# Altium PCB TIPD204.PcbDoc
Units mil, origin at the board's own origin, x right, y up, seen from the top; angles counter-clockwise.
Board outline 2010.03 x 2010.03 mil, 2 copper layers (Top Layer, Bottom Layer), stack 12.8 mil thick; 69 components, 23 nets, 172 pads, 35 vias.
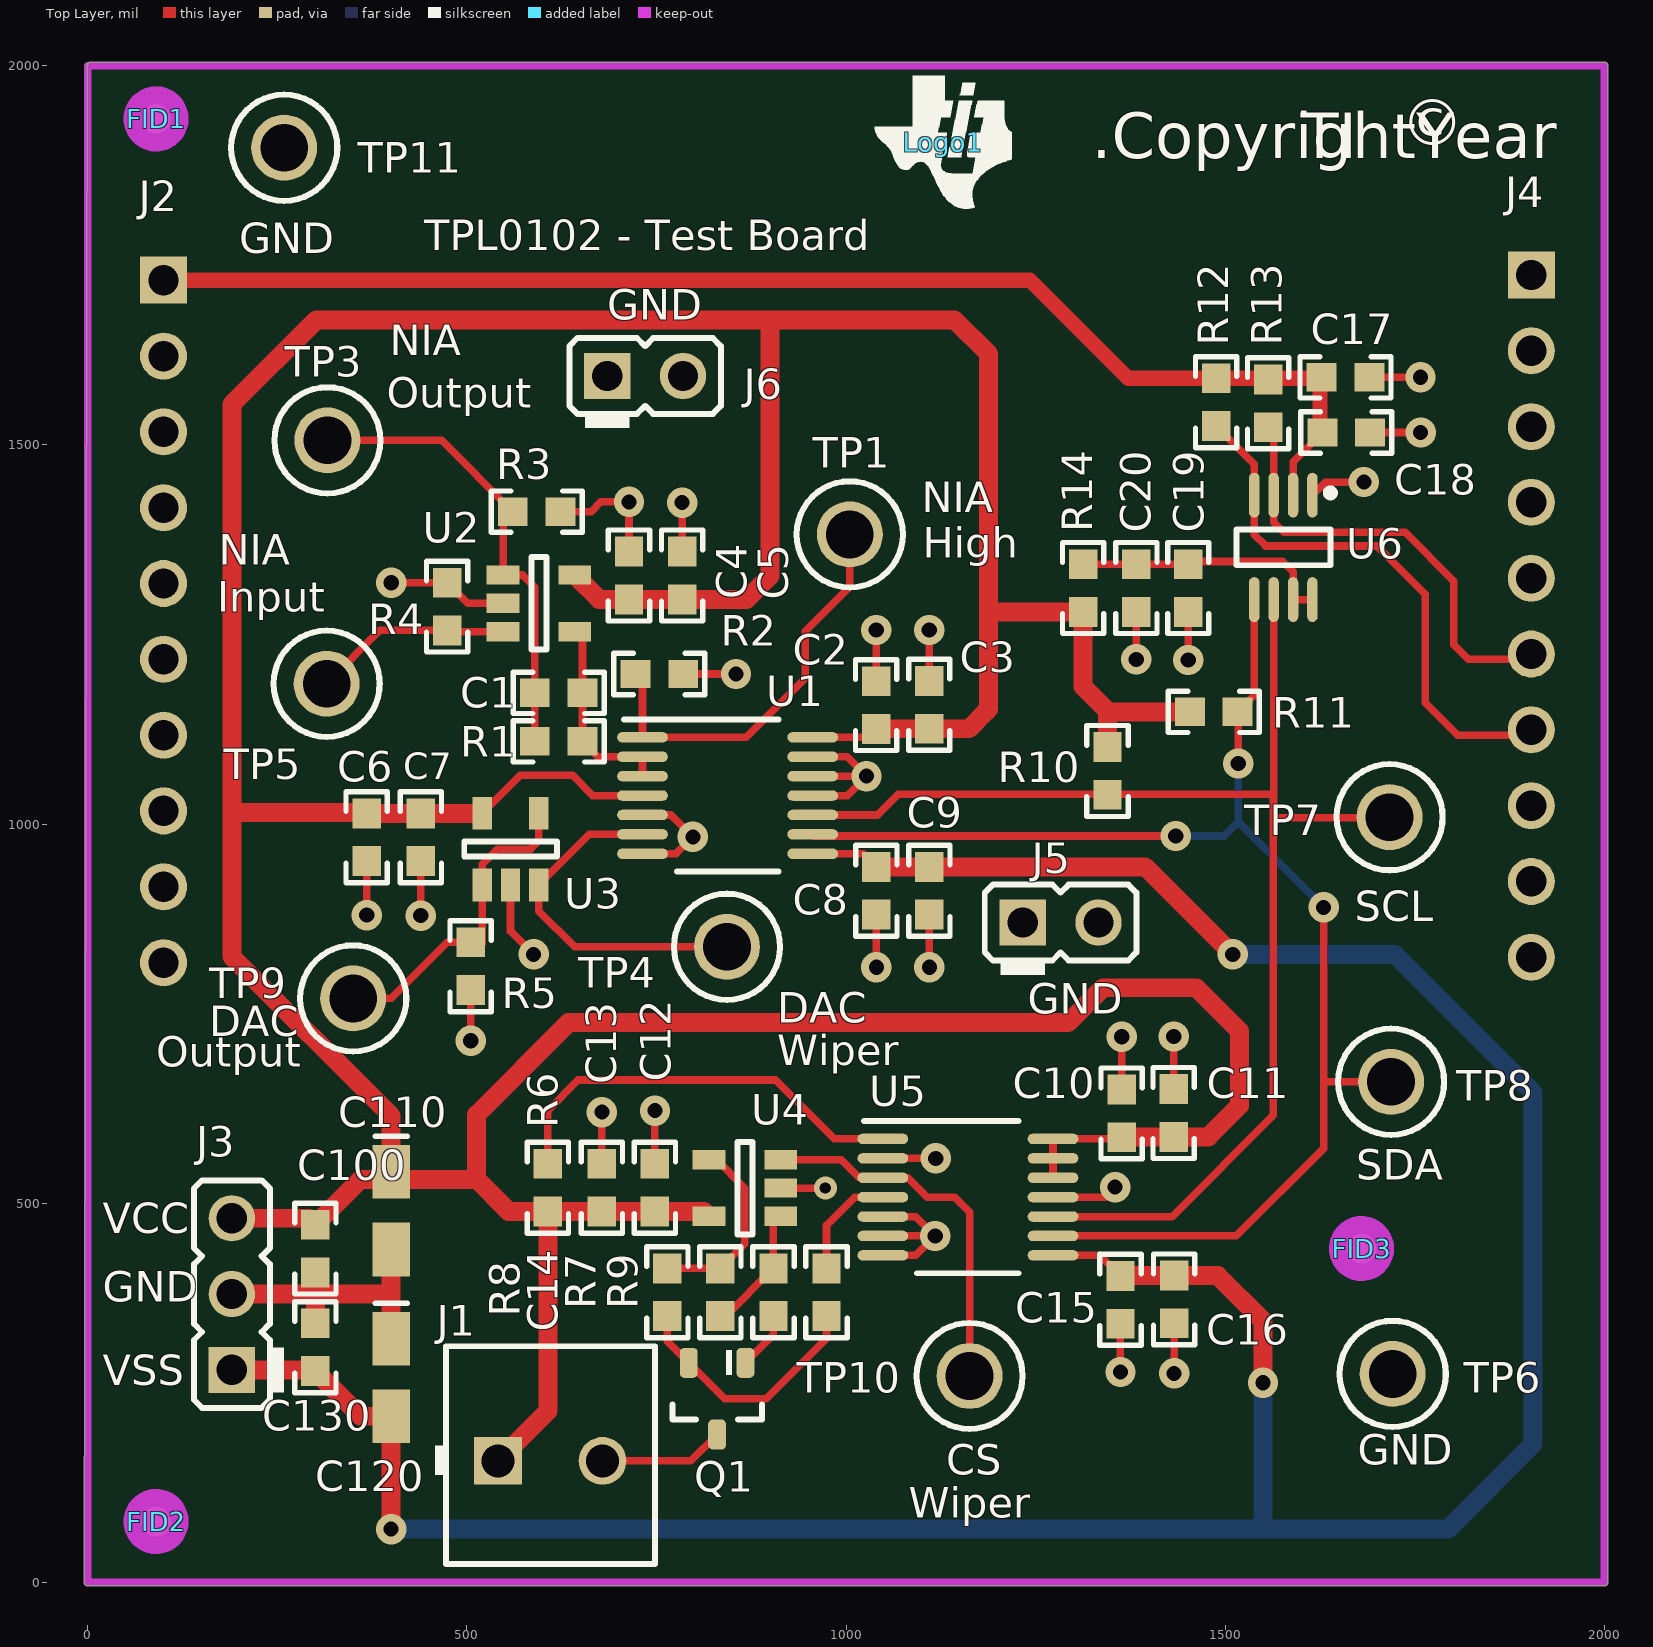
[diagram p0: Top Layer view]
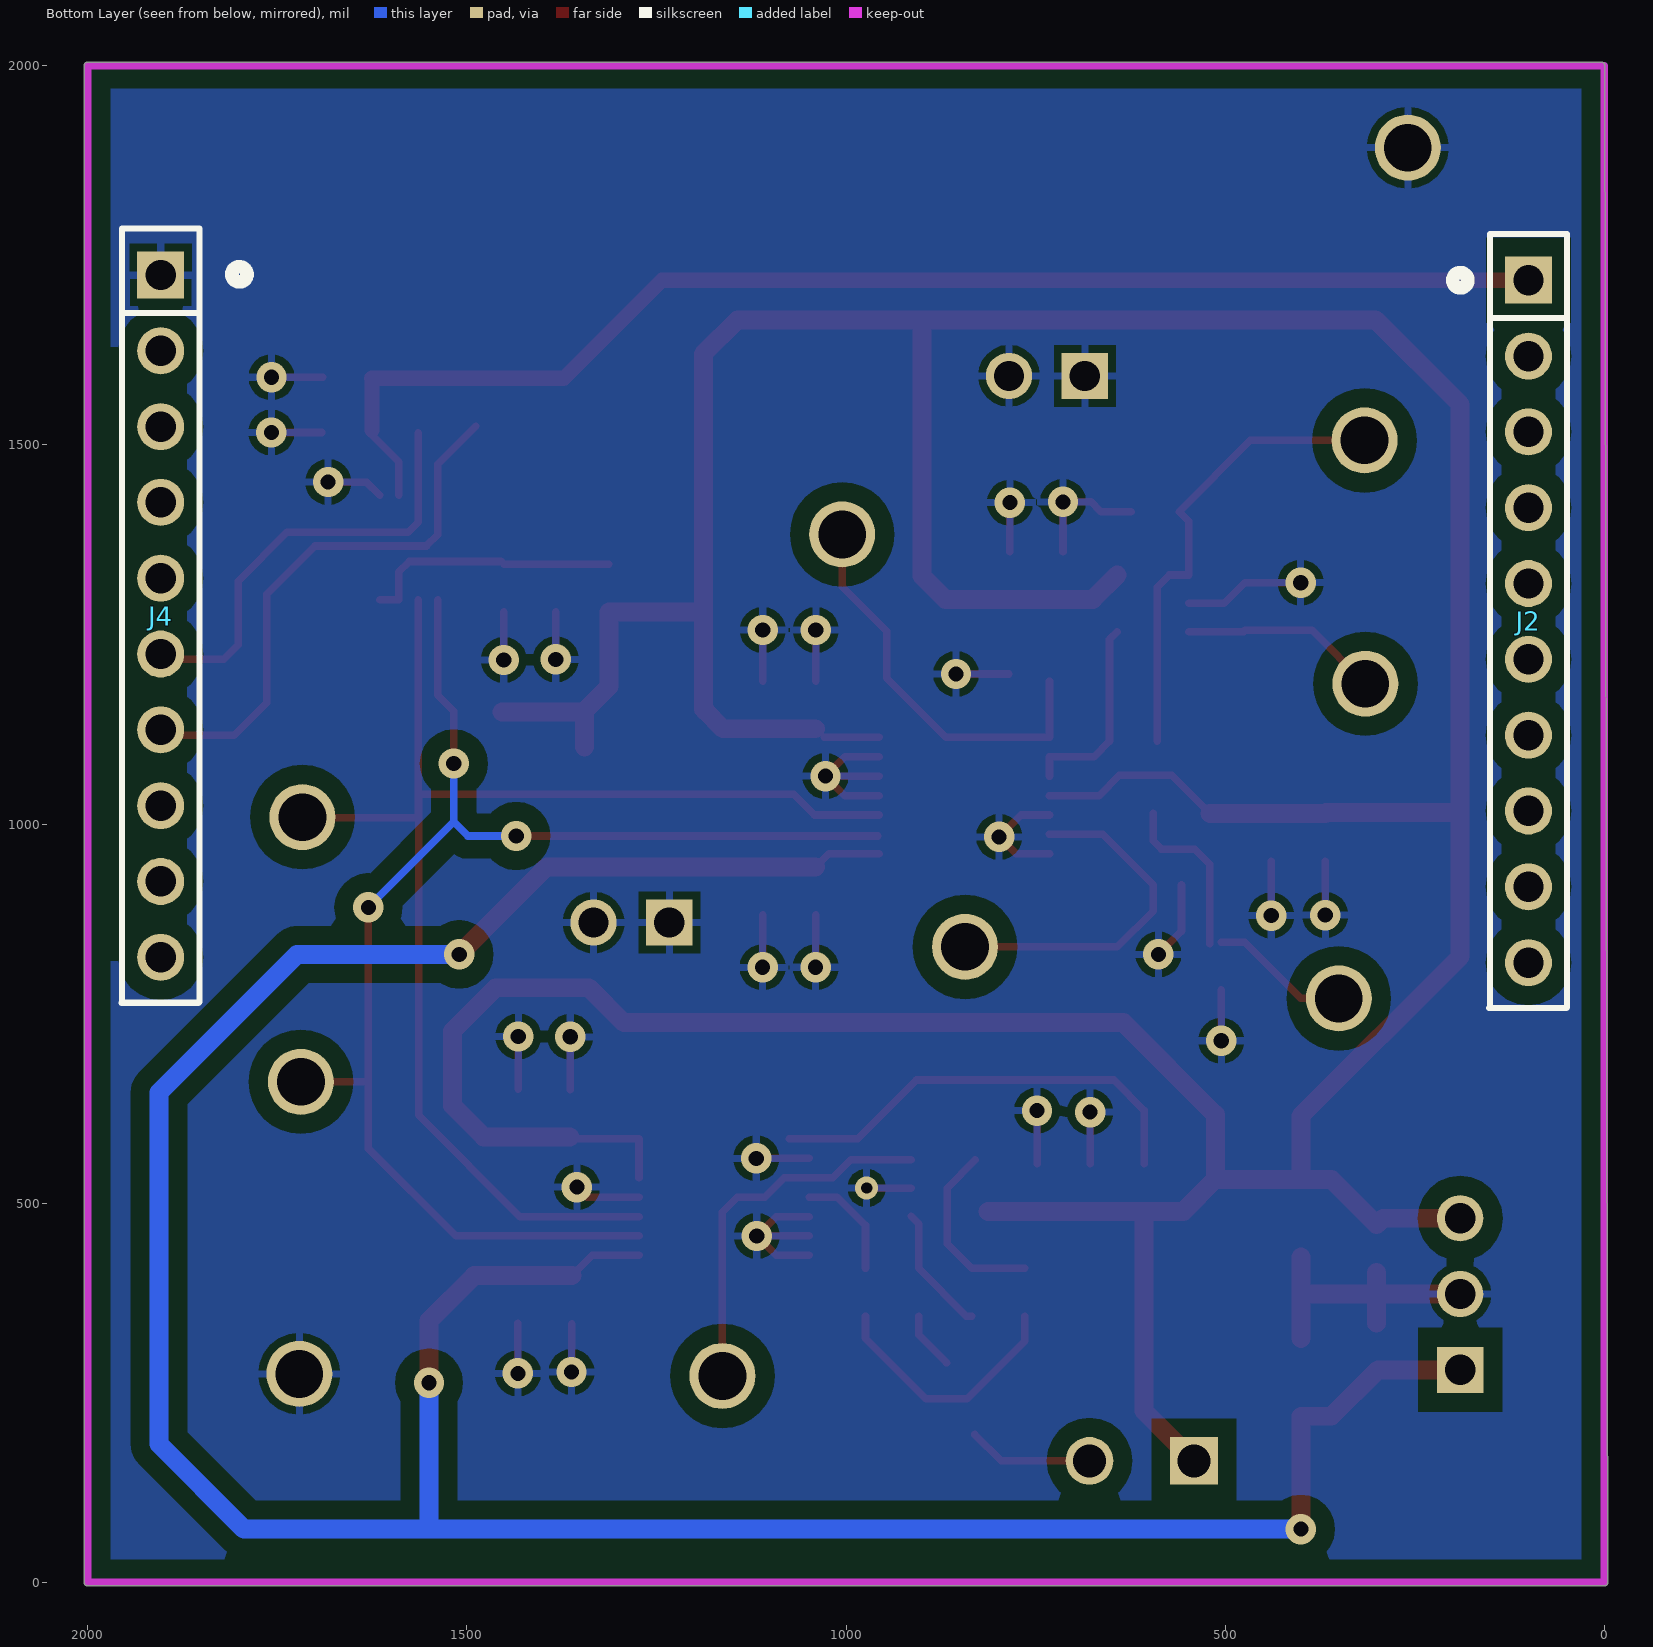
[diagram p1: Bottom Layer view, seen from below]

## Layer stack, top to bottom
Top Solder: solder mask 0.4, Solder Resist, Dk 3.5
Top Layer: signal copper 1.4
Dielectric1: core 10, FR-4, Dk 4.8
Bottom Layer: signal copper 1.4
Bottom Solder: solder mask 0.4, Solder Resist, Dk 3.5

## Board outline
0,-5.02 cw(c0,0) -5.01,0.01 -1.01,2000.01 cw(c4,2000) 4,2005.01 2000,2005.01 cw(c2000,2000) 2005.01,2000 2005.01,2 cw(c2000,2) 2004.91,1 cw(c2000,0) 2005.01,0 cw(c2000,0) 2000,-5.02

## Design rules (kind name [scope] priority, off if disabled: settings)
AcuteAngle [All] p1: minimum=4.50000000000000E+0001 checktracksonly=FALSE
AssemblyTestPointUsage [All] p1: valid=2
Clearance Clearance_Keepouts [((IsTrack Or IsArc) And Not InPoly) And IsFree and IsKeepOut vs ((IsTrack Or IsArc) And Not InPoly) And IsFree and IsKeepOut] p1: gap=0
Clearance Clearance_BoardEdge_MountingHoles [OnCopper and InComponentClass('Mounting Holes') vs IsKeepOut] p2: gap=40
Clearance Clearance_BoardEdge_Poly [OnCopper and InPoly vs IsKeepOut] p3: gap=25
Clearance Clearance_BoardEdge [OnCopper and Not InComponentClass('Logo') and not InComponentClass('FiducialMark') and not InRegion(1000,500,4000,800) and Not IsKeepout vs IsKeepOut] p4: gap=20
Clearance Clearance_Poly [InPolygon] p5: gap=25
Clearance [All] p6: gap=7.87
ComponentClearance ComponentClearance_MountingHoles_FiducialMarks [InComponentClass('Mounting Holes') vs InComponentClass('FiducialMark')] p1: gap=10 collisioncheckmode=3 verticalgap=10 showdistances=FALSE
ComponentClearance ComponentClearance_Shunt [InComponentClass('Header') vs InComponentClass('Shunt')] p2: gap=0 collisioncheckmode=3 verticalgap=0 showdistances=FALSE
ComponentClearance ComponentClearance_Logo [InComponentClass('Logo')] p3: gap=10 collisioncheckmode=3 verticalgap=10 showdistances=FALSE
ComponentClearance ComponentClearance_ScrewToNut [(HasFootprint('NY PMS 440 0025 PH')) vs (HasFootprint('Keystone_1902C'))] p4: gap=5 collisioncheckmode=3 verticalgap=10 showdistances=FALSE
ComponentClearance ComponentClearance_MountingHoles [InComponentClass('Mounting Holes')] p5: gap=20 collisioncheckmode=3 verticalgap=100000 showdistances=FALSE
ComponentClearance ComponentClearance_SmallPassives [HasFootprint('0201*') or HasFootprint('0402*') or HasFootprint('0508') or HasFootprint('0603*') or HasFootprint('0612') or HasFootprint('0805*') or HasFootprint('0815*') or HasFootprint('0830*') or HasFootprint('1206*') or HasFootprint('1210*') or HasFootprint('1808*') or HasFootprint('1812*') or HasFootprint('1825*') or HasFootprint('2010*') or HasFootprint('2220*') or HasFootprint('2225*') or HasFootprint('2512*') or HasFootprint('2728*') or HasFootprint('3518*') vs HasFootprint('0201*') or HasFootprint('0402*') or HasFootprint('0508') or HasFootprint('0603*') or HasFootprint('0612') or HasFootprint('0805*') or HasFootprint('0815*') or HasFootprint('0830*') or HasFootprint('1206*') or HasFootprint('1210*') or HasFootprint('1808*') or HasFootprint('1812*') or HasFootprint('1825*') or HasFootprint('2010*') or HasFootprint('2220*') or HasFootprint('2225*') or HasFootprint('2512*') or HasFootprint('2728*') or HasFootprint('3518*')] p6: gap=20 collisioncheckmode=3 verticalgap=10 showdistances=FALSE
ComponentClearance ComponentClearance_THtoSMT [IsThruComponent vs IsSMTComponent] p7: gap=20 collisioncheckmode=3 verticalgap=30 showdistances=FALSE
ComponentClearance ComponentClearance_THtoTH [IsThruComponent vs IsThruComponent] p8: gap=20 collisioncheckmode=3 verticalgap=30 showdistances=FALSE
ComponentClearance [All] p9: gap=40 collisioncheckmode=3 verticalgap=10 showdistances=FALSE
DiffPairsRouting [All] p1: maxlimit=100 minlimit=10 mostfreqgap=10 toplayer_minwidth=15 toplayer_maxwidth=15 toplayer_prefwidth=15 bottomlayer_minwidth=15 bottomlayer_maxwidth=15 bottomlayer_prefwidth=15 maxuncoupledlength=1000
FabricationTestPointUsage TestPointUsage [All] p1: valid=2 allowmultiple=FALSE
FabricationTestpoint Testpoint [All] p1: side=3 testpointundercomponent=TRUE minsize=40 maxsize=100 preferedsize=60 minholesize=0 maxholesize=40 preferedholesize=32 testpointgrid=1 allowsidetop=TRUE allowsidebottom=TRUE usegrid=TRUE gridtolerance=0.01
FanoutControl Fanout_LCC [IsLCC] p1: bgadir=Out bgaviamode=Centered fanoutstyle=Auto fanoutdirection=Alternating viagrid=1 // Fanout_LCC (Default Rule)
FanoutControl Fanout_BGA [IsBGA] p2: bgadir=Out bgaviamode=Centered fanoutstyle=Auto fanoutdirection=Alternating viagrid=1 // Fanout_BGA (Default Rule)
FanoutControl Fanout_Default [All] p4: bgadir=Out bgaviamode=Centered fanoutstyle=Auto fanoutdirection=Alternating viagrid=1 // Fanout_Default (Default Rule)
FanoutControl Fanout_Small [(CompPinCount < 5)] p5: bgadir=Out bgaviamode=Centered fanoutstyle=Auto fanoutdirection=OutThenIn viagrid=1 // Fanout_Small (Default Rule)
HoleSize [All] p1: absolutevalues=TRUE maxlimit=251 minlimit=8 maxpercent=80.000 minpercent=20.000
MinimumAnnularRing MinimumAnnularRing_ThermalPadVias [IsVia and InAnyComponent] p1: minimumring=5.91
MinimumAnnularRing [All] p2: minimumring=5
MinimumSolderMaskSliver MinimumSolderMaskSliver_Logo [InComponentClass('Logo') vs InComponentClass('Logo')] p1: minsoldermaskwidth=0.7
MinimumSolderMaskSliver [All] p2: minsoldermaskwidth=3.94
PlaneConnect [All] p1: planeconnectstyle=Relief reliefexpansion=10 reliefentries=4 reliefconductorwidth=10 reliefairgap=10
PolygonConnect [All] p1: connectstyle=Relief reliefconductorwidth=10 reliefentries=4 polygonreliefangle="90 Angle" airgapwidth=10
RoutingVias ThermalPadVias [IsVia and InAnyComponent] p1: holewidth=7.87 width=19.68 viastyle="Through Hole" minholewidth=7.87 minwidth=19.68 maxholewidth=12.99 maxwidth=23.62
RoutingVias [All] p2: holewidth=16 width=34 viastyle="Through Hole" minholewidth=7.87 minwidth=15 maxholewidth=40 maxwidth=65
SilkToBoardRegionClearance [Not ((IsComment or IsDesignator) And (Hide <> 'False')) and not InRegion(1000,500,4000,800)] p1:
SilkToSilkClearance SilkToSilkClearance_Pb-FreeLogo [(HasFootprint('Pb-Free_Overlay_Medium') OR HasFootprint('Pb-Free_Overlay_Small')) vs (HasFootprint('Pb-Free_Overlay_Medium') OR HasFootprint('Pb-Free_Overlay_Small'))] p1: silktosilkclearance=0
SilkToSilkClearance [All] p2: silktosilkclearance=5
SilkToSolderMaskClearance "Silk to Solder Mask Opening" [All] p1: minsilkscreentomaskgap=1 clearancetoexposedcopper=FALSE
SolderMaskExpansion [All] p1: expansion=1.97
UnpouredPolygon [All] p1: allowunpoured=FALSE
Width [All] p1: maxlimit=100 minlimit=8 preferedwidth=10 checkconnectedcopper=TRUE
14 further rules are at their usual default settings.

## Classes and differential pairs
component class Header: J3 J5 J6
component class Logo: Logo1
component class TPL0102_Applications_Hardware: FID1 FID2 FID3 ZZ1 ZZ2 ZZ3 ZZ4
component class FiducialMark: FID1 FID2 FID3
component class AssemblyNote: ZZ1 ZZ2 ZZ3 ZZ4
component class TPL0102_Applications: C1 C2 C3 C4 C5 C6 C7 C8 C9 C10 C11 C12 C13 C14 C15 C16 C17 C18 C19 C20 C100 C110 C120 C130 J2 J3 J4 J5 J6 Logo1 Q1 R1 R2 R3 R4 R5 R6 R7 R8 R9 R10 R11 R12 R13 R14 TP1 TP3 TP4 TP5 TP6 TP7 TP8 TP9 TP10 TP11 U1 U2 U3 U4 U5 U6

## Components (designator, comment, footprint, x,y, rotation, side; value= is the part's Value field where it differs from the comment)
C1 "GRM1885C2A150JA01D" 0603 621,1173 r0 top
C2 "C0603C104J3RAC" 0603 1039.84,1156.83 r90 top
C3 "06033C101KAT2A" 0603 1109.84,1157.14 r90 top
C4 "06033C101KAT2A" 0603 713.84,1327.83 r90 top
C5 "C0603C104J3RAC" 0603 783.84,1327.83 r90 top
C6 "06033C101KAT2A" 0603 367.84,982.52 r270 top
C7 "C0603C104J3RAC" 0603 439.15,982.51 r270 top
C8 "06033C101KAT2A" 0603 1040.01,912 r270 top
C9 "GRM188R71E104KA01D" 0603 1110.01,912 r270 top
C10 "C0603C104J3RAC" 0603 1363.67,618.27 r90 top
C11 "06033C101KAT2A" 0603 1432.21,618.82 r90 top
C12 "06033C101KAT2A" 0603 747.97,520.39 r90 top
C13 "C0603C104J3RAC" 0603 677.97,520.39 r90 top
C14 "06035A102KAT2A" 0603 834.3,382.39 r90 top
C15 "06033C101KAT2A" 0603 1361.97,372.39 r270 top
C16 "C0603C104J3RAC" 0603 1432.81,372.94 r270 top
C17 "C0603C104J3RAC" 0603 1658.84,1589.2 r0 top
C18 "06033C101KAT2A" 0603 1659.83,1516.34 r0 top
C19 "C0603C104J3RAC" 0603 1451.38,1311.2 r270 top
C20 "06033C101KAT2A" 0603 1382.84,1311.2 r270 top
C100 "C0603C104J3RAC" 0603 300,440 r270 top
C110 "293D106X96R3A2TE3" 3216-18 400,490 r270 top
C120 "293D106X96R3A2TE3" 3216-18 400,270 r270 top
C130 "C0603C104J3RAC" 0603 300,310 r270 top
FID1 "Fiducial" Fiducial10-20 90,1930 r0 top
FID2 "Fiducial" Fiducial10-20 90,80 r0 top
FID3 "Fiducial" Fiducial10-20 1680,440 r0 top
J1 "39357-0002" Molex_39357-0002 610,160 r0 top
J2 "PPTC101LFBN-RC" CONN_PPTC101LFBN-RC 99.84,1267.2 r90 bottom
J3 "GBC03SAAN" Sullins_Gxx03SAAN 190,380 r90 top
J4 "PPTC101LFBN-RC" CONN_PPTC101LFBN-RC 1903.84,1274.2 r90 bottom
J5 "GBC02SAAN" Sullins_Gxx02SAAN 1283,870 r0 top
J6 "GBC02SAAN" Sullins_Gxx02SAAN 735,1591 r0 top
Logo1 "Texas Instruments" TI_Symbol_Overlay_Small 1128,1899 r0 top
Q1 "SI2304DDS-T1-GE3" SOT-23 830,242 r270 top
R1 "RC0603FR-07100KL" 0603 621,1109 r180 top
R2 "RC0603FR-07100RL" 0603 753.84,1197.83 r0 top
R3 "CRCW060310K0FKEA" 0603 592,1412 r180 top
R4 "CRCW060350R0FKEA" 0603 473.83,1286.77 r270 top
R5 "CRCW060310K0FKEA" 0603 505,812.5 r90 top
R6 "RG1608P-153-B-T5" 0603 606.67,520.39 r90 top
R7 "RG1608P-201-B-T5" 0603 904.3,382.39 r270 top
R8 "RG1608P-103-B-T5" 0603 764.3,382.39 r270 top
R9 "RG1608P-122-B-T5" 0603 974.3,382.39 r90 top
R10 "CRCW06031K54FKEA" 0603 1345,1070 r90 top
R11 "CRCW06031K54FKEA" 0603 1485,1148 r180 top
R12 "CRCW06031K02FKEA" 0603 1488.34,1556.34 r90 top
R13 "CRCW06031K02FKEA" 0603 1556.84,1554.88 r90 top
R14 "CRCW0603200KFKEA" 0603 1312.84,1311.2 r270 top
TP1 "5007" Keystone5007 1005,1382 r0 top
TP3 "5007" Keystone5007 316,1506 r0 top
TP4 "5009" Keystone5009 843,838 r0 top
TP5 "5007" Keystone5007 315,1185 r0 top
TP6 "5006" Keystone5006 1721.02,274.73 r0 top
TP7 "5005" Keystone5005 1717,1009 r0 top
TP8 "5005" Keystone5005 1719,660 r0 top
TP9 "5009" Keystone5009 350,770 r0 top
TP10 "5008" Keystone5008 1163,272 r0 top
TP11 "5006" Keystone5006 259,1892 r0 top
U1 "TPL0102-100PWR" PW0014A_N 843.84,1037.51 r0 top
U2 "OPA316IDBVR" DBV0005A_N 595,1291 r0 top
U3 "OPA320AIDBVR" DBV0005A_N 557.52,966.83 r90 top
U4 "OPA317IDBV" DBV0005A_N 866.67,519.84 r180 top
U5 "TPL0102-100PWR" PW0014A_N 1160.83,507.84 r0 top
U6 "PCA9306DCTR" DCT0008A_N 1576.84,1364.88 r270 top
ZZ1 "This Assembly Note is for PCB labels only" AssemblyNoteLabel 185,3938 r0 top
ZZ2 "These assemblies are ESD sensitive, ESD precautions shall be observed." AssemblyNote 185,3829.11 r0 top
ZZ3 "These assemblies must be clean and free from flux and all contaminants. Use of no clean flux is not acceptable." AssemblyNote 185,3740.56 r0 top
ZZ4 "These assemblies must comply with workmanship standards IPC-A-610 Class 2, unless otherwise specified." AssemblyNote 185,3652 r0 top

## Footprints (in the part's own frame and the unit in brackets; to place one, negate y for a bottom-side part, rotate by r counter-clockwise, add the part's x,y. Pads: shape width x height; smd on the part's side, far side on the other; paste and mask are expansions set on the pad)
0603 [mm] "0603 from SM-752 data"
  rect 1x0.95 smd: 1(-0.8,0) 2(0.8,0)
  silkscreen extent -1.52,-0.69 1.52,0.69, body extent -0.87,-0.47 0.87,0.47, height 0.85
3216-18 [mm] "Medium density IPC, based on Kemet T495 dimensions"
  rect 1.8x1.25 smd: 1(-1.3,0) 2(1.3,0)
  silkscreen extent -2.49,-0.54 -2.49,0.54, body extent -1.7,-0.9 1.7,0.9, height 1.8
AssemblyNote [mil] "Assembly Note"
AssemblyNoteLabel [mil] "Assembly Note for PCB Labels"
CONN_PPTC101LFBN-RC [mil] "SULLINS"
  rect 62x62 hole 40: 1(450,0)
  round 62 hole 40.16: 2(350,0) 3(250,0) 4(150,0) 5(50,0) 6(-50,0) 7(-150,0) 8(-250,0) 9(-350,0) 10(-450,0)
  silkscreen extent -510,-51 511,100, body extent -510,-50 510,50, height 336
DBV0005A_N [mm] "SOT23, 5-Leads, Body 2.9x1.6mm, Pitch 0.95mm, Lead Span 2.8mm, IPC Medium Density"
  rect 1.1x0.65 smd: 1(-1.2,0.95) 2(-1.2,0) 3(-1.2,-0.95) 4(1.2,-0.95) 5(1.2,0.95)
  silkscreen extent -0.25,-1.55 0.25,1.55, body extent -1.42,-1.46 1.42,1.46, height 1.08
DCT0008A_N [mm] "TSOP, 8-Leads, Body 3x2.8mm, Pitch 0.65mm, IPC Medium Density"
  oval 1.5x0.35 smd: 1(-1.75,0.975) 2(-1.75,0.325) 3(-1.75,-0.325) 4(-1.75,-0.975) 5(1.75,-0.975) 6(1.75,-0.325) 7(1.75,0.325) 8(1.75,0.975)
  silkscreen extent -1.95,-1.57 0.6,1.7, body extent -1.45,-1.57 1.45,1.58, height 1.3
Fiducial10-20 [mm]
  round 1 smd mask+0.5: 1(0,0)
  Top Layer keep-out circle w1.178: c0,0 r0.5
Keystone5005 [mil] "Keystone Compact loops"
  round 87 hole 63: 1(0,0)
  silkscreen extent -70,-70 70,70, body extent -63,-63 62,63, height 225
Keystone5006 [mil] "Keystone Compact loops"
  round 87 hole 63: 1(0,0)
  silkscreen extent -70,-70 70,70, body extent -63,-63 62,63, height 225
Keystone5007 [mil] "Keystone Compact loops"
  round 87 hole 63: 1(0,0)
  silkscreen extent -70,-70 70,70, body extent -63,-63 62,63, height 225
Keystone5008 [mil] "Keystone Compact loops"
  round 87 hole 63: 1(0,0)
  silkscreen extent -70,-70 70,70, body extent -63,-63 62,63, height 225
Keystone5009 [mil] "Keystone Compact loops"
  round 87 hole 63: 1(0,0)
  silkscreen extent -70,-70 70,70, body extent -63,-63 62,63, height 225
Molex_39357-0002 [mm] "Terminal Block, 3.5 mm, 2x1, TH"
  rect 1.6x1.6 hole 1.1: 1(-1.75,0)
  round 1.6 hole 1.1: 2(1.75,0)
  silkscreen extent -3.86,-3.45 3.5,3.84, body extent -3.55,-3.45 3.56,3.84, height 8.51
PW0014A_N [mm] "TSOP, 14-Leads, Body 5x4.4mm, Pitch 0.65mm, IPC Medium Density"
  oval 1.7x0.35 smd: 1(-2.85,1.95) 2(-2.85,1.3) 3(-2.85,0.65) 4(-2.85,0) 5(-2.85,-0.65) 6(-2.85,-1.3) 7(-2.85,-1.95) 8(2.85,-1.95) 9(2.85,-1.3) 10(2.85,-0.65) 11(2.85,0) 12(2.85,0.65) 13(2.85,1.3) 14(2.85,1.95)
  silkscreen extent -3.47,-2.55 1.7,2.55, body extent -3.21,-2.5 3.21,2.5, height 0.98
SOT-23 [mm] "SOT23, 3-Leads, Body 2.9x1.3mm, Pitch 0.95mm, Lead Span 2.5mm, IPC Medium Density"
  rrect50% 1x0.6 smd: 1(-1.2,0.95) 2(-1.2,-0.95) 3(1.2,0)
  silkscreen extent -1.63,-1.5 0.7,1.5, body extent -1.16,-1.45 1.21,1.45, height 1
Sullins_Gxx02SAAN [mm] "Header, 2.54 mm, 2x1, TH"
  rect 1.55x1.55 hole 1.016: 1(-1.27,0)
  round 1.55 hole 1.016: 2(1.27,0)
  silkscreen extent -2.54,-1.75 2.54,1.27, body extent -2.54,-1.27 2.54,1.27, height 8.38
Sullins_Gxx03SAAN [mm] "Header, 2.54 mm, 3x1, TH"
  rect 1.55x1.55 hole 1.016: 1(-2.54,0)
  round 1.55 hole 1.016: 2(0,0) 3(2.54,0)
  silkscreen extent -3.81,-1.75 3.81,1.27, body extent -3.81,-1.27 3.81,1.27, height 8.38
TI_Symbol_Overlay_Small [mil]
  silkscreen extent -90,-88 91,88

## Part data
C1: "CAP, CERM, 15 pF, 100 V, +/- 5%, C0G/NP0, 0603"
C2 C5 C7 C10 C13 C16 C17 C19 C100 C130: "CAP, CERM, 0.1 µF, 25 V, +/- 5%, X7R, 0603"
C3 C4 C6 C8 C11 C12 C15 C18 C20: "CAP, CERM, 100 pF, 25 V, +/- 10%, X7R, 0603"
C9: "CAP, CERM, 0.1 µF, 25 V, +/- 10%, X7R, 0603"
C14: "CAP, CERM, 1000 pF, 50 V, +/- 10%, C0G/NP0, 0603"
C110 C120: "CAP, TA, 10 µF, 6.3 V, +/- 10%, 3.4 ohm, SMD"
FID1 FID2 FID3: "Fiducial mark.  There is nothing to buy or mount."
J1: "Terminal Block, 3.5 mm, 2x1, Tin, TH"
J2 J4: "Receptacle, 100mil, 10x1, Tin, TH"
J3: "Header, 2.54 mm, 3x1, Gold, TH"
J5 J6: "Header, 2.54 mm, 2x1, Gold, TH"
Logo1: library part TI_Logo, "Texas Instrument Corporate Signature"
Q1: "MOSFET, N-CH, 30 V, 3.3 A, SOT-23"
R1: "RES, 100 k, 1%, 0.1 W, 0603"
R2: "RES, 100, 1%, 0.1 W, 0603"
R3 R5: "RES, 10.0 k, 1%, 0.1 W, 0603"
R4: "RES, 50, 1%, 0.1 W, 0603"
R6: "RES, 15.0 k, 0.1%, 0.1 W, 0603"
R7: "RES, 200, 0.1%, 0.1 W, 0603"
R8: "RES, 10.0 k, 0.1%, 0.1 W, 0603"
R9: "RES, 1.20 k, 0.1%, 0.1 W, 0603"
R10 R11: "RES, 1.54 k, 1%, 0.1 W, 0603"
R12 R13: "RES, 1.02 k, 1%, 0.1 W, 0603"
R14: "RES, 200 k, 1%, 0.1 W, 0603"
TP1 TP3 TP5: "Test Point, Compact, White, TH"
TP4 TP9: "Test Point, Compact, Yellow, TH"
TP6 TP11: "Test Point, Compact, Black, TH"
TP7 TP8: "Test Point, Compact, Red, TH"
TP10: "Test Point, Compact, Orange, TH"
U1 U5: "256-TAPS DUAL CHANNEL DIGITAL POTENTIOMETER WITH NON-VOLATILE MEMORY, PW0014A"
U2: "10-MHz, Low-Power, Low-Noise, RRIO, 1.8-V CMOS Operational Amplifier, DBV0005A"
U3: "Precision, 20 MHz, 0.9 pA Ib, RRIO, CMOS Operational Amplifier, 1.8 to 5.5 V, -40 to 125 degC, 5-pin SOT23 (DBV0005A), Green (RoHS & no Sb/Br)"
U4: "Low-Offset, Rail-to-Rail I/O Operational Amplifier, DBV0005A"
U6: "Dual Bi-Directional I2C-Bus and SMBus Voltage Level-Translator, 0 to 5.5 V, -40 to 85 degC, 8-pin SM8 (DCT), Green (RoHS & no Sb/Br)"
ZZ1: library part AssemblyNoteLabel
ZZ2 ZZ3 ZZ4: library part AssemblyNote

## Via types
v1: diameter 40, hole 20, Top Layer to Bottom Layer, 34 vias
v2: diameter 30, hole 15, Top Layer to Bottom Layer, 1 vias

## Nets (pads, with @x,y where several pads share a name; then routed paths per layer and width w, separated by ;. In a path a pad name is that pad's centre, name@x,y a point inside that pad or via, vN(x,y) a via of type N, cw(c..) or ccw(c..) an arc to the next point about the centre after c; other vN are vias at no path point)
GND: C2.2 C3.2 C4.2 C5.2 C6.2 C7.2 C8.2 C9.2 C10.2 C11.2 C12.2 C13.2 C15.2 C16.2 C17.2 C18.2 C19.2 C20.2 C100.2 C110.2 C120.1 C130.1 J3.2 J4.1 J5.1 J5.2 J6.1 J6.2 R2.2 R3.1 R4.1 R5.1 TP6.1 TP11.1 U1.5 U1.7 U1.11 U1.12 U1.13 U2.2 U3.2 U4.2 U5.2 U5.5 U5.6 U5.7 U5.11 U6.1 | length 3003.5
  Top Layer w10: v1(367.84,879.84) C6.2 ; v1(400.27,1318.27) R4.1 501.1,1291 U2.2 ; v1(439.15,879.15) C7.2 ; v1(505,714.14) R5.1 ; U3.2 557.52,858.48 v1(588,828) ; R3.1 664,1412 676.83,1424.83 v1(713.84,1424.83) C4.2 ; C13.2 v1(677.97,619.97) ; U1.7 775.74,960.74 v1(798,983) 769.08,1011.92 U1.5 ; C12.2 v1(747.97,621.97) ; C5.2 v1(783.84,1423.83) ; R2.2 v1(854.84,1197.83) ; U4.2 v2(972.84,519.84) ; U1.11 1001.52,1037.51 v1(1027.12,1063.1) ; U1.12 v1(1027.12,1063.1) ; U1.13 1001.52,1088.69 v1(1027.12,1063.1) ; C2.2 v1(1039.84,1255.83) ; v1(1040.01,811.01) C8.2 ; U5.7 1092.11,431.07 v1(1117.7,456.66) ; U5.6 v1(1117.7,456.66) ; U5.5 1092.11,482.25 v1(1117.7,456.66) ; U5.2 v1(1118.34,559.02) ; C3.2 v1(1109.84,1255.84) ; v1(1110.01,810.99) C9.2 ; U5.11 1341.84,507.84 v1(1355,521) ; v1(1361.97,277.24) C15.2 ; C10.2 v1(1363.67,719.33) ; v1(1382.84,1217.16) C20.2 ; C11.2 v1(1432.21,719.79) ; v1(1432.81,275.4) C16.2 ; v1(1451.38,1216.38) C19.2 ; U6.1 1632.44,1451 v1(1683,1451) ; C17.2 v1(1757.8,1589.2) ; C18.2 v1(1757.93,1516.34)
  Top Layer w25: J3.2 298.98,380 ; C130.1 300,378.98 298.98,380 ; C100.2 300,380 ; C120.1 400,375 ; C110.2@400,428.82 400,375 ; 298.98,380 300,380 ; 300,380 395,380 400,375
LP3P6: C17.1 C18.1 J2.1 R12.2 R13.2 U6.2 | length 1746.2
  Top Layer w10: U6.2 1589.63,1477.64 C18.1
  Top Layer w20: J2.1 1242.84,1717.2 1372.2,1587.84 R12.2 C17.1@1625.98,1587.84 ; C18.1@1625.34,1519.33 C17.1@1625.34,1587.2
NetC1_1: C1.1 R1.2 R3.2 TP3.1 U2.1 | length 624.2
  Top Layer w10: TP3.1 466.5,1506 R3.2 547.76,1399.25 U2.1 573.6,1328.4 589.5,1312.5 R1.2
NetC1_2: C1.2 R1.1 U1.2 U1.3 U2.4 | length 262
  Top Layer w10: U2.4 652.5,1243.35 R1.1 672.8,1088.69 U1.2 U1.3
NetC14_1: C14.1 R7.1 U4.1 | length 168.6
  Top Layer w10: C14.1 841.31,350.9 R7.1 904.3,472.83 U4.1
NetC14_2: C14.2 R8.1 U4.4 | length 242.3
  Top Layer w10: R8.1 C14.2 866.67,446.26 866.67,519.84 U4.4@829.27,557.24
NetC19_1: C19.1 C20.1 R14.1 U6.7 U6.8 | length 341
  Top Layer w10: R14.1 C20.1 C19.1 ; C19.1@1454.89,1346.2 1575.84,1346.2 1589.63,1332.4 U6.7 U6.8
NetJ1_2: J1.2 Q1.3 | length 165.5
  Top Layer w10: J1.2 795.24,160 Q1.3
NetJ4_6: J4.6 R13.1 U6.3 | length 578.1
  Top Layer w10: R13.1@1564.04,1516.18 U6.3 1564.04,1397.99 1577.47,1384.57 1737.47,1384.57 1801.84,1320.2 1801.84,1236.2 1820.84,1217.2 J4.6@1899.84,1217.2
NetJ4_7: J4.7 R12.1 U6.4 | length 718.7
  Top Layer w10: R12.1 1538.45,1474.73 U6.4 1538.45,1381.58 1553.34,1366.69 1700.34,1366.69 1763.84,1303.2 1763.84,1160.2 1806.84,1117.2 J4.7@1899.84,1117.2
NetQ1_1: Q1.1 R7.2 | length 76.9
  Top Layer w10: Q1.1 904.3,326.14 R7.2
NetQ1_2: Q1.2 R8.2 R9.1 | length 336.9
  Top Layer w10: R8.2 764.3,317.54 Q1.2 839.84,242 894.63,242 974.3,321.67 R9.1
NetR2_1: R2.1 TP1.1 U1.1 | length 535.2
  Top Layer w10: R2.1@731.63,1188.54 U1.1 868.28,1114.28 946,1192 946,1254.17 1005,1313.17 TP1.1
NetR4_2: R4.2 TP5.1 U2.3 | length 260.2
  Top Layer w10: TP5.1 385.28,1255.28 R4.2 ; R4.2@475.51,1253.6 U2.3
NetR5_2: R5.2 TP9.1 U3.1 U3.4 | length 414.6
  Top Layer w10: TP9.1 400,770 473.99,843.99 R5.2 ; R5.2@520.12,841.92 U3.1 520.12,947.12 539.83,966.83 583.83,966.83 594.93,977.93 U3.4
NetR6_2: R6.2 U5.1 | length 587
  Top Layer w10: R6.2 606.67,622.09 646.97,662.39 906.97,662.39 984.75,584.61 U5.1 U5.1@1074.54,584.61
NetR9_2: R9.2 U5.4 | length 146.5
  Top Layer w10: R9.2 974.3,470.72 1011.42,507.84 U5.4
NetTP4_1: TP4.1 U1.6 U3.3 | length 466.4
  Top Layer w10: U1.6 661.67,986.33 U3.3 594.93,885.07 642,838 TP4.1
NetTP10_1: TP10.1 U4.3 U5.3 | length 493.8
  Top Layer w10: U4.3 993.76,557.24 1017.57,533.43 U5.3 1081.57,533.43 1107.15,507.85 1143.15,507.85 1163,488 TP10.1
SCL: R10.1 TP7.1 U1.10 U5.10 U6.6 | length 1828.4
  Top Layer w10: U1.10 1041.56,1011.92 1069.15,1039.5 1563.55,1039.5 1563.55,615.8 1430,482.25 U5.10 ; U6.6 1564.04,1008.04 TP7.1@1716.04,1008.04
SDA: R11.1 TP8.1 U1.9 U5.9 U6.5 | length 1839.9
  Top Layer w10: U1.9@958.18,984.2 v1(1434.84,984.2) ; U5.9 1514.66,456.66 1630,572 1630,660 ; v1(1517.34,1079.69) 1517.34,1148.84 1538.45,1169.96 U6.5 ; v1(1630,890) 1630,660 ; TP8.1 1630,660
  Bottom Layer w10: v1(1434.84,984.2) 1498.87,984.2 1517.34,1002.66 ; v1(1517.34,1079.69) 1517.34,1002.66 ; v1(1630,890) 1517.34,1002.66
VCC: C2.1 C3.1 C4.1 C5.1 C6.1 C7.1 C10.1 C11.1 C12.1 C13.1 C100.1 C110.1 J1.1 J3.3 R6.1 R10.2 R11.2 R14.2 U1.4 U1.14 U2.5 U3.5 U4.5 U5.12 U5.13 U5.14 | length 7100.5
  Top Layer w10: U3.5@520.06,1014.01 U3.5 570.15,1064.1 639.56,1064.1 666.15,1037.51 U1.4 ; U1.14 C2.1@1028.79,1114.28 ; U5.12 U5.13 U5.14 C10.1@1361.51,584.61
  Top Layer w25: J3.3 291.5,480 C100.1 359.68,531.18 C110.1@400,531.18 ; 191.8,1015.2 C6.1@366.65,1015.2 ; 301.64,1665 190,1553.36 190,825 400,615 C110.1@400,531.18 ; 306.04,1665 899,1665 ; C6.1 U3.5@520.06,1014.01 ; J1.1 606.67,225.57 R6.1 ; U2.5 674.31,1296.33 C4.1 C5.1 868.97,1296.33 900,1327.36 900,1664 899,1665 ; U4.5@812.97,488.9 R6.1 ; C2.1@1040.15,1125.65 C3.1 1162.29,1125.65 1185.84,1149.2 1185.84,1151.36 ; 1188,1151.36 1188,1620 1143,1665 899,1665 ; 1190.7,1279.7 R14.2 1312.84,1181.16 1346,1148 ; R10.2 1345,1147 1346,1148 ; C10.1@1364.22,587.33 C11.1 1477.9,587.33 1518.97,628.39 1518.97,727.03 1462,784 1339,784 1293,738 634,738 512.72,616.72 512.72,531.18 ; R11.2 1346,1148 ; C110.1@400,531.18 512.72,531.18 ; 512.72,531.18 555,488.9 R6.1
VSS: C8.1 C9.1 C15.1 C16.1 C120.2 C130.2 J3.1 U1.8 U5.8 | length 4068.5
  Top Layer w10: U1.8 1022.77,960.74 C8.1 ; U5.8 1334.79,431.07 C15.1@1361.42,404.44
  Top Layer w25: J3.1 298.5,280 C130.2 359.69,218.82 C120.2 v1(400,70) ; C8.1 C9.1 1394.5,943.5 v1(1510,828) ; C15.1@1361.42,404.44 C16.1 1490.56,404.44 1550,345 v1(1550,263)
  Bottom Layer w25: v1(400,70) 1550,70 ; v1(1510,828) 1724,828 1906,646 1906,182 1794,70 1550,70 ; v1(1550,263) 1550,70
pads on no net: FID1.1 FID2.1 FID3.1 J2.2 J2.3 J2.4 J2.5 J2.6 J2.7 J2.8 J2.9 J2.10 J4.2 J4.3 J4.4 J4.5 J4.8 J4.9 J4.10

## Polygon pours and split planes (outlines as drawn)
GND on Bottom Layer "Top Overlay-No Net" (solid, remove dead copper, pour order 12): 0,0 1998,0 2000,2 2000,2000 4,2000 0,1996 0,-5

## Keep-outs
Keep-Out Layer:
  lines w10: 0,3455 ccw(c0,3450) -5,3450 cw(c0,3450) 0,3455 ; 0,3455 4950,3455 ; 4950,3455 cw(c4950,3450) 4955,3450 ; 4950,3455 cw(c4950,3450) 4955,3450 ; 4955,0 cw(c4950,0) 4950,-5 ccw(c4950,0) 4955,0 ; 4955,0 4955,3450 ; 0,0 0,2000 2000,2000 2000,0 0,0

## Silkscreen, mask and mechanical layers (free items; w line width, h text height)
Top Overlay:
  text ".CopyrightYear" at 1324,1878 h60
  text "TI" at 1600,1878 h60
  text "©" at 1732,1875 h105
  text "TPL0102 - Test Board" at 444,1757 h40
  text "GND" at 200,1753 h40
  text "GND" at 685,1665 h40
  text "NIA" at 398,1618 h40
  text "Output" at 394,1549 h40
  text "NIA" at 1100,1411 h40
  text "High" at 1101,1351 h40
  text "NIA" at 173,1342 h40
  text "Input" at 171,1280 h40
  text "SCL" at 1671,872 h40
  text "GND" at 1240,750 h40
  text "DAC" at 909,738 h40
  text "DAC" at 160,720 h40
  text "Wiper" at 909,682 h40
  text "Output" at 90,680 h40
  text "SDA" at 1673,531 h40
  text "VCC" at 20,460 h40
  text "GND" at 20,370 h40
  text "VSS" at 20,260 h40
  text "GND" at 1675,155 h40
  text "CS" at 1132,142 h40
  text "Wiper" at 1083,85 h40
M1 Board Outline:
  lines w10: 0,0 0,2000 2000,2000 2000,0 0,0
M2 Board Dimensions:
  rectangle: 0,-275 125,-150
  rectangle: 125,-400 500,-275
  lines w7: 0,-275 1000,-275 ; 125,-400 125,-150 ; 250,-400 250,-150 ; 500,-400 500,-150 ; 750,-400 750,-150 ; 0,-400 1000,-400 1000,-150 0,-150 0,-400
  text ".Layer_Name" at 577,-858.49 h60
M3 3D STEP Top:
  text ".Layer_Name" at 577,-858.49 h60
M4 3D STEP Bottom:
  text ".Layer_Name" at 577,-858.49 h60
M5 Assembly Top:
  lines w10: -292,-930.17 6308,-930.17 ; -292,-726.83 6310,-726.83 ; -292,-523.5 -292,-1133.5 3713,-1133.5 6310,-1133.5 6310,-523.5 -291.5,-523.5 -291.5,-1133.5 1284,-1133.5 ; 2173,-1133.5 2173,-523.5 ; 3440,-726.83 3440,-523.5 ; 4280,-726.83 4280,-523.5 ; 4902,-1140 4902,-937.17
  text "COMPONENTS MARKED 'DNP' SHOULD NOT BE POPULATED." at 1153.5,-318.5 h60
  text "ASSEMBLY VARIANT:" at 1153,-434 h60
  text ".VariantName" at 2189,-434 h60
  text "PCB VIEWED FROM TOP SIDE" at -228.5,-655.67 h60
  text "BOARD #:" at 2248,-655.67 h60
  text ".PRJ_Number" at 2793.5,-655.67 h60
  text "REV:" at 3638,-655.67 h60
  text ".PCB_Rev" at 3929.5,-655.67 h60
  text "SVN REV:" at 4476,-655.67 h60
  text ".VersionControl_RevNumber" at 4982,-655.67 h60
  text "TID #:" at 2248,-859 h60
  text ".TID" at 2793.5,-859 h60
  text "PLOT NAME =" at -228.5,-1064.34 h60
  text ".plot_File_Name" at 577,-1064.34 h60
  text "GENERATED    :" at 2250,-1064.34 h60
  text ".Print_Date" at 3119.5,-1064.34 h60
  text ".Print_Time" at 3848.5,-1064.34 h60
  text "TEXAS INSTRUMENTS" at 5113,-1064.34 h60
M6 Assembly Bottom:
  lines w10: -292.5,-727.33 6309.5,-727.33 ; -290.5,-930.67 6309.5,-930.67 ; 1115.5,-1140.5 1115.5,-937.67 ; 1737.5,-727.33 1737.5,-524 ; 2577.5,-727.33 2577.5,-524 ; 3844.5,-1134 3844.5,-524 ; 4733.5,-1134 6309,-1134 6309,-524 -292.5,-524 -292.5,-1134 2304.5,-1134 6309.5,-1134 6309.5,-524
  text "COMPONENTS MARKED 'DNP' SHOULD NOT BE POPULATED." at 6102,-318 h60
  text ".VariantName" at 5058,-434 h60
  text "ASSEMBLY VARIANT:" at 6097,-434 h60
  text ".VersionControl_RevNumber" at 1035.5,-656.17 h60
  text "SVN REV:" at 1541.5,-656.17 h60
  text ".PCB_Rev" at 2088,-656.17 h60
  text "REV:" at 2379.5,-656.17 h60
  text ".PRJ_Number" at 3224,-656.17 h60
  text "BOARD #:" at 3769.5,-656.17 h60
  text "PCB VIEWED FROM BOTTOM SIDE" at 6246,-656.17 h60
  text ".TID" at 3224,-859.5 h60
  text "TID #:" at 3769.5,-859.5 h60
  text "TEXAS INSTRUMENTS" at 904.5,-1064.84 h60
  text ".Print_Time" at 2169,-1064.84 h60
  text ".Print_Date" at 2898,-1064.84 h60
  text "GENERATED    :" at 3767.5,-1064.84 h60
  text ".plot_File_Name" at 5440.5,-1064.84 h60
  text "PLOT NAME =" at 6246,-1064.84 h60
M9 Title Sheet:
  drawing of 57 lines, arcs and shapes, not listed
  text "1" at 739.84,8036.5 h70
  text "2" at 3235.5,8036.5 h70
  text "3" at 5724.84,8036.5 h70
  text "4" at 8231.51,8036.5 h70
  text "5" at 10730.5,8036.5 h70
  text "6" at 13235.5,8036.5 h70
  text "A" at -416.5,6893.5 h70
  text "A" at 14383.5,6893.5 h70
  text "B" at -416.5,4513.5 h70
  text "B" at 14383.5,4513.5 h70
  text "C" at -416.5,2138.5 h70
  text "C" at 14383.5,2138.5 h70
  text "PROJECT TITLE:" at 11343.5,277.5 h45
  text ".PRJ_Title" at 11393.5,144.17 h70
  text "DESIGNED FOR:" at 11343.5,-23.5 h45
  text ".PRJ_Customer" at 11393.5,-163.5 h70
  text "D" at -416.5,-231.5 h70
  text "D" at 14383.5,-231.5 h70
  text "FILE NAME:" at 11343.5,-323.5 h45
  text ".PCB_File_Name_No_Path" at 11393.5,-443.5 h70
  text "Texas Instruments (TI) and/or its licensors do not warrant the accuracy or completeness of this specification" at 6374,-605.34 h45
  text "ENGINEER:" at 11343.5,-613.5 h45
  text "LAYOUT BY:" at 12848.5,-613.5 h45
  text "or any information contained therein. TI and/or its licensors do not warrant that this design will meet" at 6329.01,-718 h45
  text ".PRJ_Engineer" at 11393.5,-768.49 h70
  text ".PCB_Layout" at 12899,-768.49 h70
  text "the specifications, will be suitable for your application or fit for any particular purpose, or will operate in" at 6329.01,-830.67 h45
  text ".Layer_Name" at 577,-858.49 h60
  text "ALTIUM DESIGNER VERSION:" at 12848.5,-923.5 h45
  text "an implementation. TI and/or its licensors do not warrant that the design is production worthy. You should" at 6329.01,-943.33 h45
  text "completely validate and test your design implementation to confirm the system functionality for your application." at 6374,-1056 h45
  text ".print_Scale" at 11393.5,-1056.83 h70
  text ".Application_BuildNumber" at 12899,-1056.83 h70
  text "1" at 739.84,-1263.5 h70
  text "2" at 3235.5,-1263.5 h70
  text "3" at 5724.84,-1263.5 h70
  text "4" at 8231.51,-1263.5 h70
  text "5" at 10730.5,-1263.5 h70
  text "6" at 13235.5,-1263.5 h70
M10 Fab Notes:
  drawing of 185 lines, arcs and shapes, not listed
  text "DESIGN INFORMATION" at 12381.02,5910 h60
  text "MIN. TRACK WIDTH:" at 11736.46,5730 h60
  text "8" at 12832.7,5730 h60
  text "MIL" at 12987.46,5730 h60
  text "MIN. CLEARANCE:" at 11736.46,5598 h60
  text "0.2" at 12772.7,5598 h60
  text "mm" at 12987.46,5598 h60
  text "MIN. VIA PAD SIZE:" at 11736.46,5466 h60
  text "24" at 12802.71,5466 h60
  text "MIL" at 12987.46,5466 h60
  text "0.05mm (2MIL)" at 12431.46,5324.29 h60
  text "MINIMUM ANNULAR RING" at 11407.23,5320 h60
  text "EXTERNAL" at 13139.46,5320 h60
  text "PER" at 11607.23,5202 h60
  text "IPC-D-275 CLASS 2 LEVEL C" at 11827.23,5202 h60
  text "MIL, HOLES" at 13315.46,5089.71 h60
  text "+/-" at 12923,5089 h60
  text "+/-" at 13777,5089 h60
  text "REGISTRATION TOLERANCES:" at 11407.23,5084 h60
  text "METAL" at 12607,5084 h60
  text "5" at 13183.2,5084 h60
  text "3" at 14016.2,5084 h60
  text "MIL" at 14132.46,5084 h60
  text "MATERIAL:" at 11332.46,4874.54 h60
  text "FR-4 High Tg" at 12318.9,4734.21 h60
  text "FR-408" at 11753.46,4725.64 h60
  text "X" at 12165.46,4725.64 h60
  text "OTHER" at 13241.46,4725.64 h60
  text "62 MIL (1.6mm) +/-10%" at 12073.56,4562.92 h60
  text "THICKNESS:" at 11407.23,4558.64 h60
  text "X" at 11945.4,4558.64 h60
  text "OTHER" at 13358.46,4558.64 h60
  text "TOLERANCE:" at 11407.23,4400.64 h60
  text "X" at 12246.53,4400.64 h60
  text "ANSI IPC-6012 TYPE 3 CLASS 2" at 12433.48,4400.64 h60
  text "OTHER +/-" at 12433.46,4244.64 h60
  text "BOW & TWIST:" at 11407.23,4087.64 h60
  text "X" at 12246.53,4087.64 h60
  text "ANSI IPC-6012 TYPE 3 CLASS 2" at 12433.48,4087.64 h60
  text "OTHER +/-" at 12433.46,3929.13 h60
  text "DRILLING:" at 11332.46,3790.64 h60
  text "REFERENCE:" at 11407.23,3673.64 h60
  text "X" at 12055.46,3673.64 h60
  text "AS SHOWN" at 12242.46,3673.64 h60
  text "X" at 12956.46,3673.64 h60
  text "NC_DRILL FILES" at 13093.46,3673.64 h60
  text "PTH MIN COPPER THICKNESS:" at 11407.23,3515.64 h60
  text "X" at 12757.46,3515.64 h60
  text "1MIL" at 12894.46,3515.64 h60
  text "OTHER" at 13391.46,3515.64 h60
  text "BOARD FINISH:" at 11332.46,3356.64 h60
  text "SILKSCREEN:" at 11487.68,3238.64 h60
  text "X" at 12436.46,3238.64 h60
  text "TOP" at 12562.46,3238.64 h60
  text "X" at 12946.46,3238.64 h60
  text "BOTTOM" at 13073.46,3238.64 h60
  text "SILKSCREEN COLOR:" at 11487.68,3071.64 h60
  text "X" at 12435.42,3071.64 h60
  text "WHITE" at 12562.46,3071.64 h60
  text "OTHER" at 13073.46,3071.64 h60
  text "SOLDER RESIST COLOR:" at 11487.68,2901.64 h60
  text "X" at 12055.42,2742.44 h60
  text "GREEN" at 12182.46,2742.44 h60
  text "BLUE" at 12773.46,2742.44 h60
  text "OTHER" at 13311.46,2742.44 h60
  text "IMMERSION GOLD (ENIG)" at 12393.46,2553.92 h60
  text "ENEPIG" at 13731,2550.64 h60
  text "SURFACE FINISH:" at 11332.46,2549.64 h60
  text "X" at 12206.51,2549.64 h60
  text "IMM. TIN/SILVER OR EQUIV" at 11662,2392.64 h60
  text "OTHER" at 13093.46,2392.64 h60
  text "ARRAY/PANEL:" at 11332.46,2213.64 h60
  text "CUT AND TRIM PER MECH LAYER 1" at 12393.46,2209.35 h60
  text "N.C. ROUTE" at 12393.46,2057.64 h60
  text "X" at 13072.46,2057.64 h60
  text "V. SCORE" at 13259.46,2057.64 h60
  text "CERTIFICATION:" at 11332.46,1920.64 h60
  text "MATERIALS AND WORKMANSHIP FOR ALL PCBS" at 12057.46,1920.64 h60
  text "TO MEET OR EXCEED THE REQUIREMENTS OF:" at 12057.46,1822.64 h60
  text "X" at 11683.96,1686.13 h60
  text "ANSI IPC-A-600F CLASS ->" at 11822.96,1686.13 h60
  text "X" at 13462.02,1686.13 h60
  text "2" at 13580.96,1686.14 h60
  text "1" at 13265.96,1684.64 h60
  text "3" at 13934.96,1684.64 h60
  text "X" at 11686.02,1526.64 h60
  text "UL 94V-0" at 11822.96,1526.64 h60
  text "X" at 12498.02,1526.64 h60
  text "RoHS" at 12634.96,1526.64 h60
  text "OTHER" at 13279.36,1526.64 h60
  text "PER ORDER" at 13676.42,1526.64 h60
  text "ADDITIONAL REQUIREMENTS:" at 11332.46,1385.64 h60
  text "MICROSECTION:" at 11407.23,1270.64 h60
  text "YES" at 12312.96,1270.64 h60
  text "REQUIRED" at 13174.46,1114.49 h60
  text "BARE BOARD ELEC. TEST:" at 11407.23,1111.64 h60
  text "NONE" at 12712.96,1111.64 h60
  text "X" at 13047.46,1111.64 h60
  text "PER ORDER" at 13766.46,1111.64 h60
  text "MANUFACTURER'S UL:" at 11407.23,954.64 h60
  text "RAIL" at 12572.96,950.35 h60
  text "METAL" at 13064.77,950.35 h60
  text "X" at 13440,950 h60
  text "SILK" at 13576.46,950.35 h60
  text ".Layer_Name" at 577,-858.49 h60
M11 Gerber Information:
  lines w10: -292,-930.17 6308,-930.17 ; -292,-726.83 6310,-726.83 ; -292,-523.5 -292,-1133.5 3713,-1133.5 6310,-1133.5 6310,-523.5 -291.5,-523.5 -291.5,-1133.5 1284,-1133.5 ; 2173,-1133.5 2173,-523.5 ; 3440,-726.83 3440,-523.5 ; 4280,-726.83 4280,-523.5 ; 4902,-1140 4902,-937.17
  text "ALL ARTWORK VIEWED FROM TOP SIDE" at -228.5,-655.67 h60
  text "BOARD #:" at 2248,-655.67 h60
  text ".PRJ_Number" at 2793.5,-655.67 h60
  text "REV:" at 3638,-655.67 h60
  text ".PCB_Rev" at 3929.5,-655.67 h60
  text "SVN REV:" at 4476,-655.67 h60
  text ".VersionControl_RevNumber" at 4982,-655.67 h60
  text "LAYER NAME =" at -228.5,-858.49 h60
  text "TID #:" at 2248,-859 h60
  text ".TID" at 2793.5,-859 h60
  text "PLOT NAME =" at -228.5,-1064.34 h60
  text ".plot_File_Name" at 577,-1064.34 h60
  text "GENERATED    :" at 2250,-1064.34 h60
  text ".Print_Date" at 3119.5,-1064.34 h60
  text ".Print_Time" at 3848.5,-1064.34 h60
  text "TEXAS INSTRUMENTS" at 5113,-1064.34 h60
M12 Stackup:
  drawing of 191 lines, arcs and shapes, not listed
  text "Layer" at 9790.34,7830 h60
  text "Name" at 10200.26,7830 h60
  text "Material" at 11130,7830 h60
  text "Thickness" at 11989.77,7830 h60
  text "Constant" at 12639.6,7830 h60
  text "Board Layer Stack" at 13209.46,7830 h60
  text "1" at 9790.34,7710 h60
  text "Top Overlay" at 10200.26,7710 h60
  text "2" at 9790.34,7590 h60
  text "Top Solder" at 10200.26,7590 h60
  text "Solder Resist" at 11130,7590 h60
  text "0.40mil" at 11989.77,7590 h60
  text "3.5" at 12639.6,7590 h60
  text "3" at 9790.34,7470 h60
  text "Top Layer" at 10200.26,7470 h60
  text "Copper" at 11130,7470 h60
  text "1.40mil" at 11989.77,7470 h60
  text "4" at 9790.34,7350 h60
  text "Dielectric1" at 10200.26,7350 h60
  text "FR-4" at 11130,7350 h60
  text "59.20mil" at 11989.77,7350 h60
  text "4.8" at 12639.6,7350 h60
  text "5" at 9790.34,7230 h60
  text "Bottom Layer" at 10200.26,7230 h60
  text "Copper" at 11130,7230 h60
  text "1.40mil" at 11989.77,7230 h60
  text "6" at 9790.34,7110 h60
  text "Bottom Solder" at 10200.26,7110 h60
  text "Solder Resist" at 11130,7110 h60
  text "0.40mil" at 11989.77,7110 h60
  text "3.5" at 12639.6,7110 h60
  text "7" at 9790.34,6990 h60
  text "Bottom Overlay" at 10200.26,6990 h60
  text ".Layer_Name" at 577,-858.49 h60
M13 Component Bodies Top:
  text ".Layer_Name" at 577,-858.49 h60
M14 Component Bodies Bottom:
  text ".Layer_Name" at 577,-858.49 h60
M15 Courtyards Top:
  text ".Layer_Name" at 577,-858.49 h60
M16 Courtyards Bottom:
  text ".Layer_Name" at 577,-858.49 h60
Drill Drawing:
  circle w1: c5692.8,2921.91 r24.91
  lines w1: 5667.89,2461.08 5680.35,2461.08 5692.8,2448.63 5705.26,2461.08 5717.71,2461.08 5705.26,2473.54 5717.71,2485.99 5705.26,2485.99 5692.8,2498.45 5680.35,2485.99 5667.89,2485.99 5680.35,2473.54 5667.89,2461.08 ; 5667.89,2598.09 5692.8,2610.54 5717.71,2598.09 5705.26,2623 5717.71,2647.9 5692.8,2635.45 5667.89,2647.9 5680.35,2623 5667.89,2598.09 ; 5667.89,2797.36 5717.71,2797.36 5692.8,2747.54 5667.89,2797.36 ; 5667.89,3046.46 5667.89,3058.92 5680.35,3071.37 5667.89,3083.83 5667.89,3096.28 5680.35,3096.28 5692.8,3083.83 5705.26,3096.28 5717.71,3096.28 5717.71,3083.83 5705.26,3071.37 5717.71,3058.92 5717.71,3046.46 5705.26,3046.46 5692.8,3058.92 5680.35,3046.46 5667.89,3046.46 ; 5667.89,3195.92 5717.71,3195.92 5717.71,3245.74 5667.89,3245.74 5667.89,3195.92
  lines w12: 5600,2403.79 7719.4,2403.79 ; 5600,3300.54 7719.4,3300.54 ; 5970.67,2254.33 5970.67,3450 ; 6327.78,2254.33 6327.78,3450 ; 6989.79,2254.33 6989.79,3450 ; 7274.14,2254.33 7274.14,3450 ; 5600,2254.33 7719.4,2254.33 7719.4,3450 5600,3450 5600,2254.33
  text "Symbol" at 5689.68,3345.38 h72
  text "Quantity" at 6015.51,3345.38 h72
  text "Finished Hole Size" at 6372.62,3345.38 h72
  text "Plated" at 7034.62,3345.38 h72
  text "Hole Type" at 7318.98,3345.38 h72
  text "1" at 6015.51,3195.92 h60
  text "15.00mil (0.381mm)" at 6372.62,3195.92 h60
  text "PTH" at 7034.62,3195.92 h60
  text "Round" at 7318.98,3195.92 h60
  text "34" at 6015.51,3046.46 h60
  text "20.00mil (0.508mm)" at 6372.62,3046.46 h60
  text "PTH" at 7034.62,3046.46 h60
  text "Round" at 7318.98,3046.46 h60
  text "9" at 6015.51,2897 h60
  text "40.00mil (1.016mm)" at 6372.62,2897 h60
  text "PTH" at 7034.62,2897 h60
  text "Round" at 7318.98,2897 h60
  text "18" at 6015.51,2747.54 h60
  text "40.16mil (1.020mm)" at 6372.62,2747.54 h60
  text "PTH" at 7034.62,2747.54 h60
  text "Round" at 7318.98,2747.54 h60
  text "2" at 6015.51,2598.09 h60
  text "43.31mil (1.100mm)" at 6372.62,2598.09 h60
  text "PTH" at 7034.62,2598.09 h60
  text "Round" at 7318.98,2598.09 h60
  text "10" at 6015.51,2448.63 h60
  text "63.00mil (1.600mm)" at 6372.62,2448.63 h60
  text "PTH" at 7034.62,2448.63 h60
  text "Round" at 7318.98,2448.63 h60
  text "74 Total" at 6015.51,2299.17 h60

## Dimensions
0,-400 to 1000,-400 on M2 Board Dimensions
0,0 to 4,2005.01 on M2 Board Dimensions
0,0 to -5.01,0.01 on M2 Board Dimensions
